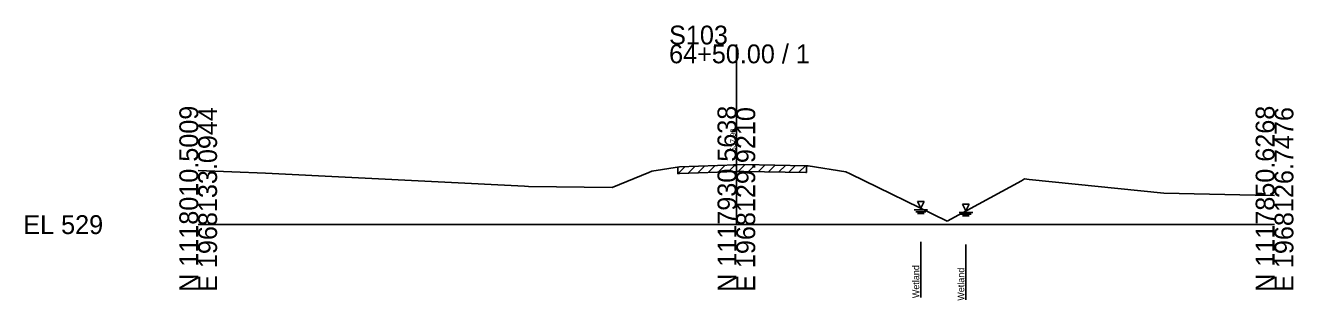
# Model space of a CAD drawing. Extents: x -26 to 163, y -10 to 45020.
# Drawn here: x -25.7 to 162.8, y 23488.7 to 23529.6 of the extents above; entities that cross this region are included whole.
import ezdxf

# ---------------------------------------------------------------- set-up
doc = ezdxf.new("R2010")
doc.units = 0
for name, color, linetype in [('RD_GPK_XS_Cell', 7, 'Continuous'), ('RD_XS_ExGround', 7, 'Continuous'), ('RD_XS_ExPaveRet', 7, 'Continuous'), ('RD_XS_EXWetland', 7, 'Continuous'), ('RD_XS_TX_Elev_EX', 7, 'Continuous')]:
    doc.layers.add(name, color=color, linetype=linetype)

msp = doc.modelspace()

# ---------------------------------------------------------------- linework, layer by layer
at = {"layer": 'RD_GPK_XS_Cell'}
for p, q in [((80, 23500), (80, 23526.8)), ((0, 23500), (80, 23500)), ((80, 23500), (160, 23500))]:
    msp.add_line(p, q, dxfattribs=at)
at = {"layer": 'RD_XS_ExGround'}
for p, q in [((67.44, 23507.94), (71.55, 23508.59)), ((71.55, 23508.59), (80, 23508.9)), ((80, 23508.9), (81.11, 23508.93)), ((81.11, 23508.93), (90.34, 23508.77)), ((90.34, 23508.77), (90.68, 23508.76)), ((90.68, 23508.76), (96.27, 23507.85)), ((0, 23508.03), (9.99, 23507.67)), ((9.99, 23507.67), (48.53, 23505.71)), ((61.56, 23505.53), (67, 23507.76)), ((67, 23507.76), (67.44, 23507.94)), ((96.27, 23507.85), (96.91, 23507.56)), ((96.91, 23507.56), (111.32, 23500.53)), ((111.32, 23500.53), (122.39, 23506.54)), ((122.39, 23506.54), (122.83, 23506.79)), ((122.83, 23506.79), (123.52, 23506.71)), ((123.52, 23506.71), (143.52, 23504.7)), ((48.53, 23505.71), (49.08, 23505.68)), ((49.08, 23505.68), (61.56, 23505.53)), ((143.52, 23504.7), (157.13, 23504.38)), ((157.13, 23504.38), (160, 23504.36))]:
    msp.add_line(p, q, dxfattribs=at)
at = {"layer": 'RD_XS_ExPaveRet'}
for p, q in [((71.29, 23507.55), (72.36, 23508.62)), ((71.29, 23507.55), (71.29, 23508.55)), ((72.79, 23507.63), (73.83, 23508.67)), ((74.29, 23507.69), (75.33, 23508.73)), ((75.79, 23507.74), (76.83, 23508.78)), ((77.29, 23507.8), (78.33, 23508.84)), ((78.79, 23507.85), (79.83, 23508.89)), ((80.29, 23507.91), (81.32, 23508.93)), ((81.79, 23507.92), (82.78, 23508.9)), ((83.29, 23507.89), (84.28, 23508.88)), ((84.79, 23507.87), (85.78, 23508.85)), ((86.29, 23507.84), (87.28, 23508.82)), ((87.79, 23507.81), (88.78, 23508.8)), ((89.29, 23507.79), (90.28, 23508.77)), ((90.43, 23508.77), (90.43, 23507.77)), ((71.29, 23507.55), (71.55, 23507.59)), ((71.55, 23507.59), (80, 23507.9)), ((80, 23507.9), (81.11, 23507.93)), ((81.11, 23507.93), (90.34, 23507.77)), ((90.34, 23507.77), (90.43, 23507.77))]:
    msp.add_line(p, q, dxfattribs=at)
at = {"layer": 'RD_XS_EXWetland'}
for p, q in [((106.93, 23503.43), (107.43, 23502.43)), ((107.93, 23503.43), (106.93, 23503.43)), ((107.43, 23502.43), (107.93, 23503.43)), ((113.63, 23503.05), (114.13, 23502.05)), ((114.63, 23503.05), (113.63, 23503.05)), ((114.13, 23502.05), (114.63, 23503.05)), ((106.43, 23502.18), (108.43, 23502.18)), ((106.68, 23501.93), (108.18, 23501.93)), ((106.93, 23501.68), (107.93, 23501.68)), ((113.13, 23501.8), (115.13, 23501.8)), ((113.38, 23501.55), (114.88, 23501.55)), ((113.63, 23501.3), (114.63, 23501.3)), ((107.43, 23497.43), (107.43, 23489.18)), ((114.13, 23497.05), (114.13, 23488.8))]:
    msp.add_line(p, q, dxfattribs=at)

# ---------------------------------------------------------------- texts
at = {"layer": 'RD_GPK_XS_Cell'}
for s, p in [('S103', (70, 23526.8)), ('64+50.00 / 1', (70, 23524)), ('EL 529', (-26, 23498.6))]:
    msp.add_text(s, height=2.8, dxfattribs=at).set_placement(p)
for s, p in [('N 1118010.5009', (0, 23490)), ('E 1968133.0944', (2.8, 23490)), ('N 1117930.5638', (80, 23490)), ('E 1968129.9210', (82.8, 23490)), ('N 1117850.6268', (160, 23490)), ('E 1968126.7476', (162.8, 23490))]:
    msp.add_text(s, height=2.8, rotation=90, dxfattribs=at).set_placement(p)
at = {"layer": 'RD_XS_EXWetland'}
for p in [(107.18, 23489.07), (113.88, 23488.69)]:
    msp.add_text('Wetland ', height=1, rotation=90, dxfattribs=at).set_placement(p)
at = {"layer": 'RD_XS_TX_Elev_EX'}
msp.add_text('537.90', height=0.8, rotation=90, dxfattribs=at).set_placement((79.9, 23510.9))

doc.saveas('drawing.dxf')
